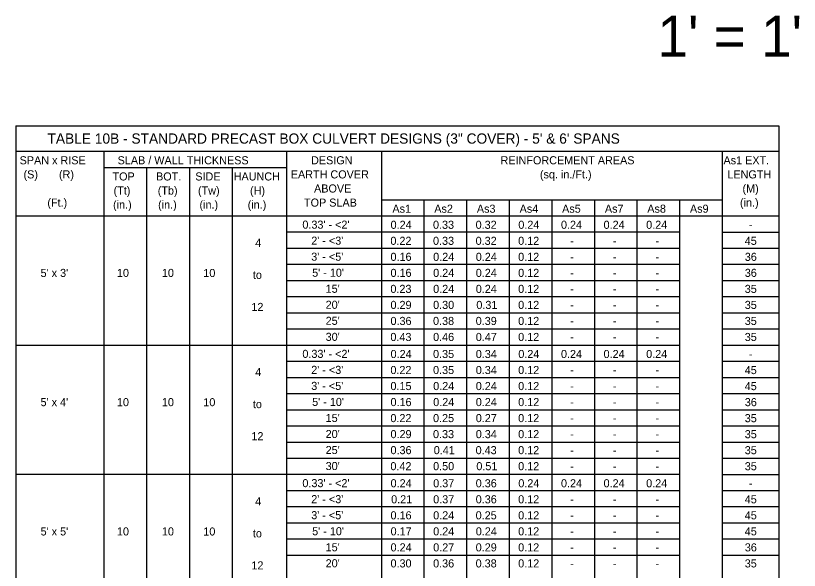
# Model space of a CAD drawing. Extents: x 10338.56 to 10340.78, y 76371.55 to 76372.62.
# Drawn here: x 10339.21 to 10339.821, y 76372.188 to 76372.621 of the extents above; entities that cross this region are included whole.
import ezdxf

# ---------------------------------------------------------------- set-up
doc = ezdxf.new("R2010")
doc.units = 0
doc.layers.add('AdhocPoint_dp', color=7, linetype='Continuous')
doc.layers.add('PlotBorder_dp', color=7, linetype='Continuous')

msp = doc.modelspace()

# ---------------------------------------------------------------- linework, layer by layer
at = {"layer": 'PlotBorder_dp'}
for p, q in [((10339.21023, 76372.53475), (10339.21023, 76371.75893)), ((10339.21023, 76372.53475), (10339.80497, 76372.53475)), ((10339.80497, 76372.53475), (10339.80497, 76371.75893)), ((10339.21023, 76372.51488), (10339.80497, 76372.51488)), ((10339.27886, 76372.51488), (10339.27886, 76371.75893)), ((10339.42131, 76372.51488), (10339.42131, 76371.75893)), ((10339.49519, 76372.51488), (10339.49519, 76371.75893)), ((10339.76078, 76372.51488), (10339.76078, 76371.75893)), ((10339.27886, 76372.50228), (10339.42131, 76372.50228)), ((10339.31222, 76372.50228), (10339.31222, 76371.75893)), ((10339.34558, 76372.50228), (10339.34558, 76371.75893)), ((10339.37895, 76372.50228), (10339.37895, 76371.75893)), ((10339.49519, 76372.47713), (10339.76078, 76372.47713)), ((10339.52839, 76372.47713), (10339.52839, 76371.75893)), ((10339.56158, 76372.47713), (10339.56158, 76371.75893)), ((10339.59478, 76372.47713), (10339.59478, 76371.75893)), ((10339.62798, 76372.47713), (10339.62798, 76371.75893)), ((10339.66118, 76372.47713), (10339.66118, 76371.75893)), ((10339.66118, 76372.47713), (10339.66118, 76371.75893)), ((10339.69438, 76372.47713), (10339.69438, 76371.75893)), ((10339.72758, 76372.47713), (10339.72758, 76371.75893)), ((10339.21023, 76372.46453), (10339.80497, 76372.46453)), ((10339.42131, 76372.45193), (10339.72758, 76372.45193)), ((10339.76078, 76372.45191), (10339.80497, 76372.45191)), ((10339.42131, 76372.43933), (10339.72758, 76372.43933)), ((10339.76078, 76372.43931), (10339.80497, 76372.43931)), ((10339.42131, 76372.42673), (10339.72758, 76372.42673)), ((10339.76078, 76372.42671), (10339.80497, 76372.42671)), ((10339.42131, 76372.41413), (10339.72758, 76372.41413)), ((10339.76078, 76372.41411), (10339.80497, 76372.41411)), ((10339.42131, 76372.40153), (10339.72758, 76372.40153)), ((10339.76078, 76372.40151), (10339.80497, 76372.40151)), ((10339.42131, 76372.38893), (10339.72758, 76372.38893)), ((10339.76078, 76372.38891), (10339.80497, 76372.38891)), ((10339.42131, 76372.37633), (10339.72758, 76372.37633)), ((10339.76078, 76372.37631), (10339.80497, 76372.37631)), ((10339.21023, 76372.36373), (10339.72758, 76372.36373)), ((10339.76078, 76372.36371), (10339.80497, 76372.36371)), ((10339.42131, 76372.35113), (10339.72758, 76372.35113)), ((10339.76078, 76372.35111), (10339.80497, 76372.35111)), ((10339.42131, 76372.33853), (10339.72758, 76372.33853)), ((10339.76078, 76372.33851), (10339.80497, 76372.33851)), ((10339.42131, 76372.32593), (10339.72758, 76372.32593)), ((10339.76078, 76372.32591), (10339.80497, 76372.32591)), ((10339.42131, 76372.31333), (10339.72758, 76372.31333)), ((10339.76078, 76372.31331), (10339.80497, 76372.31331)), ((10339.42131, 76372.30073), (10339.72758, 76372.30073)), ((10339.76078, 76372.30071), (10339.80497, 76372.30071)), ((10339.42131, 76372.28813), (10339.72758, 76372.28813)), ((10339.76078, 76372.28811), (10339.80497, 76372.28811)), ((10339.42131, 76372.27553), (10339.72758, 76372.27553)), ((10339.76078, 76372.27551), (10339.80497, 76372.27551)), ((10339.21023, 76372.26293), (10339.72758, 76372.26293)), ((10339.76078, 76372.26291), (10339.80497, 76372.26291)), ((10339.42131, 76372.25033), (10339.72758, 76372.25033)), ((10339.76078, 76372.25031), (10339.80497, 76372.25031)), ((10339.42131, 76372.23773), (10339.72758, 76372.23773)), ((10339.76078, 76372.23771), (10339.80497, 76372.23771)), ((10339.42131, 76372.22513), (10339.72758, 76372.22513)), ((10339.76078, 76372.22511), (10339.80497, 76372.22511)), ((10339.42131, 76372.21253), (10339.72758, 76372.21253)), ((10339.76078, 76372.21251), (10339.80497, 76372.21251)), ((10339.42131, 76372.19993), (10339.72758, 76372.19993)), ((10339.76078, 76372.19991), (10339.80497, 76372.19991))]:
    msp.add_line(p, q, dxfattribs=at)

# ---------------------------------------------------------------- texts
at = {"layer": 'AdhocPoint_dp'}
for s, height, p in [("1' = 1'", 0.032, (10339.71037, 76372.58867)), ('TABLE 10B - STANDARD PRECAST BOX CULVERT DESIGNS (3" COVER) - 5\' & 6\' SPANS', 0.008, (10339.23504, 76372.52082)), ('SLAB / WALL THICKNESS', 0.0063, (10339.28968, 76372.50472)), ('As1', 0.0063, (10339.50381, 76372.46696)), ('As2', 0.0063, (10339.53644, 76372.46696)), ('As3', 0.0063, (10339.56963, 76372.46696)), ('As4', 0.0063, (10339.60296, 76372.46696)), ('As5', 0.0063, (10339.63606, 76372.46696)), ('As7', 0.0063, (10339.6694, 76372.46696)), ('As8', 0.0063, (10339.70245, 76372.46696)), ('As9', 0.0063, (10339.7357, 76372.46696)), ("5' x 3'", 0.0063, (10339.22965, 76372.41686)), ('10', 0.0063, (10339.28914, 76372.41686)), ('10', 0.0063, (10339.32418, 76372.41686)), ('10', 0.0063, (10339.35647, 76372.41681)), ("5' x 4'", 0.0063, (10339.22964, 76372.31608)), ('10', 0.0063, (10339.28914, 76372.31608)), ('10', 0.0063, (10339.32418, 76372.31608)), ('10', 0.0063, (10339.35647, 76372.31602)), ("5' x 5'", 0.0063, (10339.22966, 76372.21524)), ('10', 0.0063, (10339.28914, 76372.21524)), ('10', 0.0063, (10339.32418, 76372.21524)), ('10', 0.0063, (10339.35647, 76372.21519))]:
    msp.add_text(s, height=height, dxfattribs=at).set_placement(p)
at = {"layer": 'PlotBorder_dp'}
for s, p in [('SPAN x RISE', (10339.21331, 76372.50472)), ('DESIGN', (10339.44041, 76372.50472)), ('REINFORCEMENT AREAS', (10339.58809, 76372.50472)), ('(S)       (R)', (10339.21636, 76372.49372)), ('(sq. in./Ft.)', (10339.61878, 76372.49372)), ('TOP', (10339.28569, 76372.49212)), ('BOT.', (10339.31962, 76372.49212)), ('SIDE', (10339.35021, 76372.49212)), ('HAUNCH', (10339.3801, 76372.49212)), ('EARTH COVER', (10339.42462, 76372.49372)), ('ABOVE', (10339.44276, 76372.48272)), ('(Tt)', (10339.28653, 76372.48112)), ('(Tb)', (10339.32096, 76372.48112)), ('(Tw)', (10339.35232, 76372.48112)), ('(H)', (10339.39285, 76372.48112)), ('(Ft.)', (10339.23493, 76372.47172)), ('(in.)', (10339.28614, 76372.47012)), ('(in.)', (10339.32123, 76372.47012)), ('(in.)', (10339.35347, 76372.47012)), ('(in.)', (10339.39104, 76372.47012)), ('TOP SLAB', (10339.43493, 76372.47172)), ("0.33' - <2'", (10339.43366, 76372.45452)), ('0.24', (10339.50239, 76372.45441)), ('0.33', (10339.53546, 76372.45441)), ('0.32', (10339.56866, 76372.45441)), ('0.24', (10339.60194, 76372.45441)), ('0.24', (10339.63518, 76372.45441)), ('0.24', (10339.66838, 76372.45441)), ('0.24', (10339.70157, 76372.45441)), ('-', (10339.7817, 76372.45441)), ('4', (10339.39689, 76372.44033)), ("2' - <3'", (10339.44056, 76372.44202)), ('0.22', (10339.50226, 76372.44191)), ('0.33', (10339.53546, 76372.44191)), ('0.32', (10339.56866, 76372.44191)), ('0.12', (10339.60182, 76372.44191)), ('45', (10339.77839, 76372.44191)), ('-', (10339.64245, 76372.44191)), ('-', (10339.67566, 76372.44191)), ('-', (10339.70885, 76372.44191)), ("3' - <5'", (10339.44056, 76372.42952)), ('0.16', (10339.50233, 76372.42941)), ('0.24', (10339.53559, 76372.42941)), ('0.24', (10339.56879, 76372.42941)), ('0.12', (10339.60182, 76372.42941)), ('36', (10339.77843, 76372.42941)), ('-', (10339.64245, 76372.42941)), ('-', (10339.67566, 76372.42941)), ('-', (10339.70885, 76372.42941)), ('to', (10339.39511, 76372.41533)), ("5' - 10'", (10339.44128, 76372.41702)), ('0.16', (10339.50233, 76372.41691)), ('0.24', (10339.53559, 76372.41691)), ('0.24', (10339.56879, 76372.41691)), ('0.12', (10339.60182, 76372.41691)), ('36', (10339.77843, 76372.41691)), ('-', (10339.64245, 76372.41691)), ('-', (10339.67566, 76372.41691)), ('-', (10339.70885, 76372.41691)), ("15'", (10339.45179, 76372.40452)), ('0.23', (10339.50226, 76372.40441)), ('0.24', (10339.53559, 76372.40441)), ('0.24', (10339.56879, 76372.40441)), ('0.12', (10339.60182, 76372.40441)), ('35', (10339.77839, 76372.40441)), ('-', (10339.64245, 76372.40441)), ('-', (10339.67566, 76372.40441)), ('-', (10339.70885, 76372.40441)), ('12', (10339.39393, 76372.39033)), ("20'", (10339.45179, 76372.39202)), ('0.29', (10339.50233, 76372.39191)), ('0.30', (10339.53554, 76372.39191)), ('0.31', (10339.56923, 76372.39191)), ('0.12', (10339.60182, 76372.39191)), ('35', (10339.77839, 76372.39191)), ('-', (10339.64245, 76372.39191)), ('-', (10339.67566, 76372.39191)), ('-', (10339.70885, 76372.39191)), ("25'", (10339.45179, 76372.37952)), ('0.36', (10339.50233, 76372.37941)), ('0.38', (10339.53548, 76372.37941)), ('0.39', (10339.56873, 76372.37941)), ('0.12', (10339.60182, 76372.37941)), ('35', (10339.77839, 76372.37941)), ('-', (10339.64245, 76372.37941)), ('-', (10339.67566, 76372.37941)), ('-', (10339.70885, 76372.37941)), ("30'", (10339.45179, 76372.36702)), ('0.43', (10339.50226, 76372.36691)), ('0.46', (10339.53553, 76372.36691)), ('0.47', (10339.5688, 76372.36691)), ('0.12', (10339.60182, 76372.36691)), ('35', (10339.77839, 76372.36691)), ('-', (10339.64245, 76372.36691)), ('-', (10339.67566, 76372.36691)), ('-', (10339.70885, 76372.36691)), ("0.33' - <2'", (10339.43366, 76372.35374)), ('0.24', (10339.50239, 76372.35363)), ('0.35', (10339.53549, 76372.35363)), ('0.34', (10339.56879, 76372.35363)), ('0.24', (10339.60194, 76372.35363)), ('0.24', (10339.63518, 76372.35363)), ('0.24', (10339.66838, 76372.35363)), ('0.24', (10339.70157, 76372.35363)), ('-', (10339.7817, 76372.35358)), ("2' - <3'", (10339.44056, 76372.34124)), ('4', (10339.39689, 76372.33953)), ('0.22', (10339.50226, 76372.34113)), ('0.35', (10339.53549, 76372.34113)), ('0.34', (10339.56879, 76372.34113)), ('0.12', (10339.60182, 76372.34113)), ('-', (10339.64245, 76372.34113)), ('-', (10339.67566, 76372.34113)), ('-', (10339.70885, 76372.34113)), ('45', (10339.77839, 76372.34108)), ("3' - <5'", (10339.44056, 76372.32874)), ('0.15', (10339.50229, 76372.32863)), ('0.24', (10339.53559, 76372.32863)), ('0.24', (10339.56879, 76372.32863)), ('0.12', (10339.60182, 76372.32863)), ('-', (10339.64245, 76372.32863)), ('-', (10339.67566, 76372.32863)), ('-', (10339.70885, 76372.32863)), ('45', (10339.77839, 76372.32858)), ('to', (10339.39511, 76372.31453)), ("5' - 10'", (10339.44128, 76372.31624)), ('0.16', (10339.50233, 76372.31613)), ('0.24', (10339.53559, 76372.31613)), ('0.24', (10339.56879, 76372.31613)), ('0.12', (10339.60182, 76372.31613)), ('-', (10339.64245, 76372.31613)), ('-', (10339.67566, 76372.31613)), ('-', (10339.70885, 76372.31613)), ('36', (10339.77843, 76372.31608)), ("15'", (10339.45179, 76372.30374)), ('0.22', (10339.50226, 76372.30363)), ('0.25', (10339.53549, 76372.30363)), ('0.27', (10339.5688, 76372.30363)), ('0.12', (10339.60182, 76372.30363)), ('-', (10339.64245, 76372.30363)), ('-', (10339.67566, 76372.30363)), ('-', (10339.70885, 76372.30363)), ('35', (10339.77839, 76372.30358)), ('12', (10339.39393, 76372.28953)), ("20'", (10339.45179, 76372.29124)), ('0.29', (10339.50233, 76372.29113)), ('0.33', (10339.53546, 76372.29113)), ('0.34', (10339.56879, 76372.29113)), ('0.12', (10339.60182, 76372.29113)), ('-', (10339.64245, 76372.29113)), ('-', (10339.67566, 76372.29113)), ('-', (10339.70885, 76372.29113)), ('35', (10339.77839, 76372.29108)), ("25'", (10339.45179, 76372.27874)), ('0.36', (10339.50233, 76372.27863)), ('0.41', (10339.53603, 76372.27863)), ('0.43', (10339.56866, 76372.27863)), ('0.12', (10339.60182, 76372.27863)), ('-', (10339.64245, 76372.27863)), ('-', (10339.67566, 76372.27863)), ('-', (10339.70885, 76372.27863)), ('35', (10339.77839, 76372.27858)), ("30'", (10339.45179, 76372.26624)), ('0.42', (10339.50226, 76372.26613)), ('0.50', (10339.53554, 76372.26613)), ('0.51', (10339.56923, 76372.26613)), ('0.12', (10339.60182, 76372.26613)), ('-', (10339.64245, 76372.26613)), ('-', (10339.67566, 76372.26613)), ('-', (10339.70885, 76372.26613)), ('35', (10339.77839, 76372.26608)), ("0.33' - <2'", (10339.43366, 76372.2529)), ('0.24', (10339.50239, 76372.2528)), ('0.37', (10339.5356, 76372.2528)), ('0.36', (10339.56873, 76372.2528)), ('0.24', (10339.60194, 76372.2528)), ('0.24', (10339.63518, 76372.2528)), ('0.24', (10339.66838, 76372.2528)), ('0.24', (10339.70157, 76372.2528)), ('-', (10339.7817, 76372.2528)), ('4', (10339.39689, 76372.23873)), ("2' - <3'", (10339.44056, 76372.2404)), ('0.21', (10339.50283, 76372.2403)), ('0.37', (10339.5356, 76372.2403)), ('0.36', (10339.56873, 76372.2403)), ('0.12', (10339.60182, 76372.2403)), ('45', (10339.77839, 76372.2403)), ('-', (10339.64245, 76372.2403)), ('-', (10339.67566, 76372.2403)), ('-', (10339.70885, 76372.2403)), ("3' - <5'", (10339.44056, 76372.2279)), ('0.16', (10339.50233, 76372.2278)), ('0.24', (10339.53559, 76372.2278)), ('0.25', (10339.56869, 76372.2278)), ('0.12', (10339.60182, 76372.2278)), ('45', (10339.77839, 76372.2278)), ('-', (10339.64245, 76372.2278)), ('-', (10339.67566, 76372.2278)), ('-', (10339.70885, 76372.2278)), ('to', (10339.39511, 76372.21373)), ("5' - 10'", (10339.44128, 76372.2154)), ('0.17', (10339.5024, 76372.2153)), ('0.24', (10339.53559, 76372.2153)), ('0.24', (10339.56879, 76372.2153)), ('0.12', (10339.60182, 76372.2153)), ('45', (10339.77839, 76372.2153)), ('-', (10339.64245, 76372.2153)), ('-', (10339.67566, 76372.2153)), ('-', (10339.70885, 76372.2153)), ("15'", (10339.45179, 76372.2029)), ('0.24', (10339.50239, 76372.2028)), ('0.27', (10339.5356, 76372.2028)), ('0.29', (10339.56873, 76372.2028)), ('0.12', (10339.60182, 76372.2028)), ('36', (10339.77843, 76372.2028)), ('-', (10339.64245, 76372.2028)), ('-', (10339.67566, 76372.2028)), ('-', (10339.70885, 76372.2028)), ('12', (10339.39393, 76372.18873)), ("20'", (10339.45179, 76372.1904)), ('0.30', (10339.50234, 76372.1903)), ('0.36', (10339.53553, 76372.1903)), ('0.38', (10339.56868, 76372.1903)), ('0.12', (10339.60182, 76372.1903)), ('35', (10339.77839, 76372.1903)), ('-', (10339.64245, 76372.1903)), ('-', (10339.67566, 76372.1903)), ('-', (10339.70885, 76372.1903))]:
    msp.add_text(s, height=0.0063, dxfattribs=at).set_placement(p)
for s, p in [('As1 EXT.', (10339.76182, 76372.50472)), ('LENGTH', (10339.76485, 76372.49372)), ('(M)', (10339.77665, 76372.48272)), ('(in.)', (10339.77469, 76372.47172))]:
    msp.add_text(s, height=0.0063, rotation=360, dxfattribs=at).set_placement(p)

doc.saveas('drawing.dxf')
